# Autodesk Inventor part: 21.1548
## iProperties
Created: 2012-02
Part Number: 21.1548
Document SubType Name: Modeling
Designer: Administrator
Density: 7.85 g/cm^3
Material: Steel
Mass: 3.18067 g
Surface Area: 5.0468 cm^2
Volume: 0.405181 cm^3
Description: M8 Hex Nut Thin
Translation Standard: STEP AP203
FileName: 90695A040.step
PreProcessor: SolidWorks 2007
PostProcessor: Build: 236a, Release: 2009 RTM - Date: Fri 02/22/2008
Sent Units: MM
Uncertainty: 1e-05
Author: Administrator
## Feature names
1. Base1
